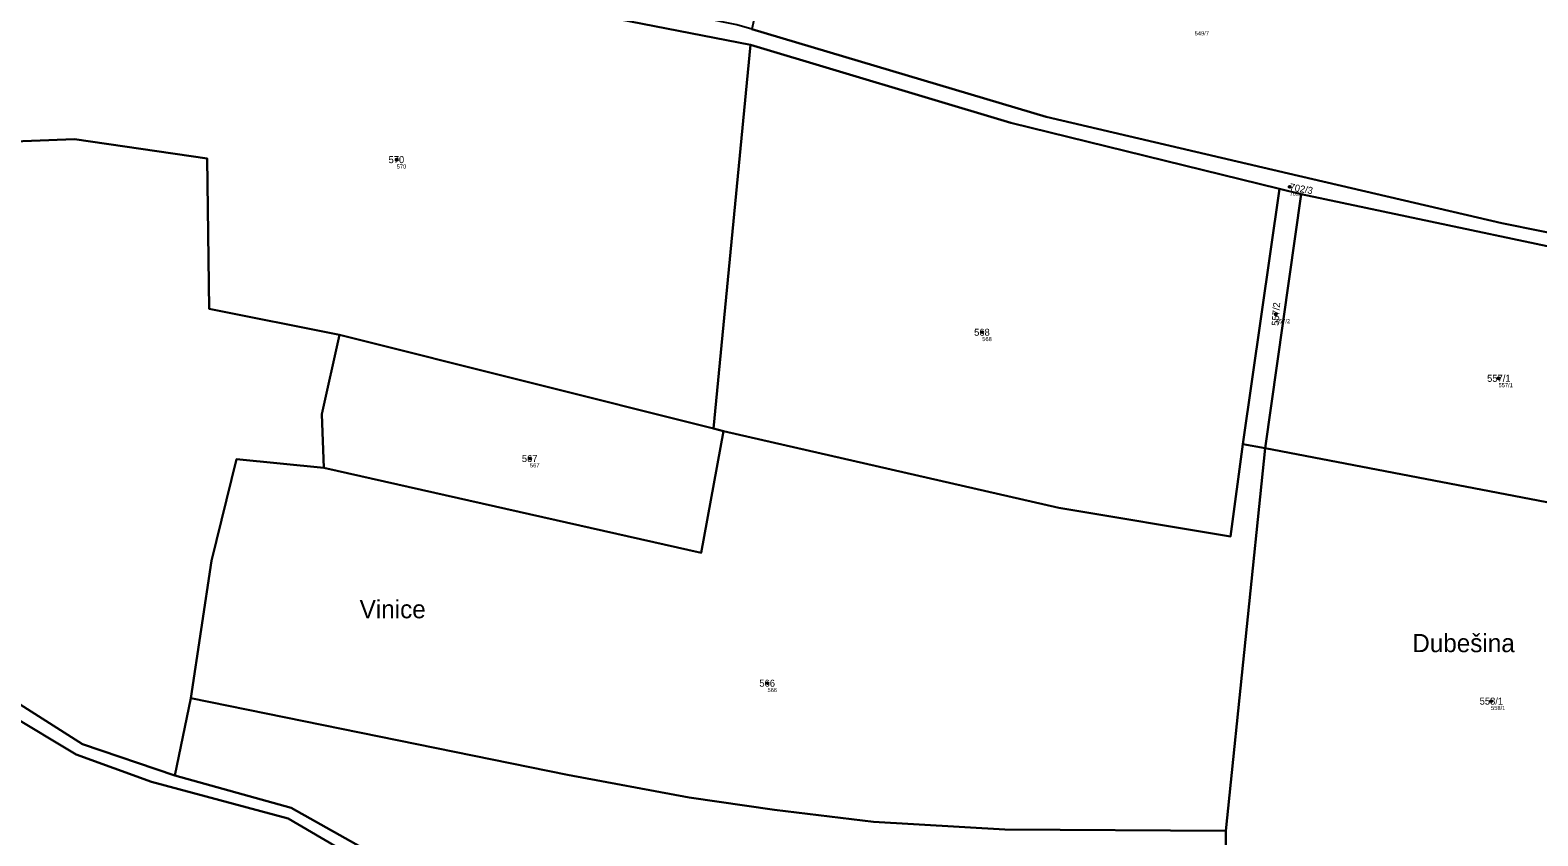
# Model space of a CAD drawing. Extents: x -767985 to -763816, y -1059600 to -1057360.
# Drawn here: x -764545.8 to -764180.2, y -1058967.5 to -1058772.1 of the extents above; entities that cross this region are included whole.
import ezdxf

# ---------------------------------------------------------------- set-up
doc = ezdxf.new("R2010")
doc.units = 0
for name, color, linetype in [('Definiční body', 7, 'Continuous'), ('Hranice parcel', 7, 'Continuous'), ('Parcelní čísla', 7, 'Continuous'), ('Polygon parcely', 7, 'Continuous'), ('Pop  PČ popisy', 7, 'Continuous')]:
    doc.layers.add(name, color=color, linetype=linetype)

msp = doc.modelspace()

# ---------------------------------------------------------------- linework, layer by layer
at = {"layer": 'Definiční body'}
for centre in [(-764456.89, -1058803.50994), (-764240.38, -1058810.07994), (-764243.73, -1058841.01994), (-764314.92, -1058845.35994), (-764189.75, -1058856.52994), (-764424.57, -1058875.97994), (-764366.99, -1058930.44994), (-764191.56, -1058934.78994)]:
    msp.add_circle(centre, 0.25, dxfattribs=at)
at = {"layer": 'Hranice parcel'}
for p, q in [((-764371.09, -1058775.68), (-764380.09, -1058868.72)), ((-764242.88, -1058810.57), (-764251.71, -1058872.53)), ((-764237.59, -1058811.87), (-764246.31, -1058873.43)), ((-764242.88, -1058810.57), (-764237.59, -1058811.87)), ((-764380.09, -1058868.72), (-764470.72, -1058846.01)), ((-764377.65, -1058869.33), (-764380.09, -1058868.72)), ((-764246.31, -1058873.43), (-764255.86, -1058966.23)), ((-764251.71, -1058872.53), (-764246.31, -1058873.43)), ((-764246.31, -1058873.43), (-764129.55, -1058895.82)), ((-764506.78, -1058934.04), (-764510.68, -1058952.79)), ((-764255.86, -1058966.23), (-764255.54, -1058994.61))]:
    msp.add_line(p, q, dxfattribs=at)
for points in [[(-764504.93, -1058762.17), (-764465.63, -1058763.92), (-764435.08, -1058763.17), (-764371.09, -1058775.68)], [(-764117.67, -1058835.76), (-764150.51, -1058826.7), (-764188.92, -1058818.94), (-764240.71, -1058806.89), (-764299.39, -1058793.13), (-764370.8, -1058771.89)], [(-764371.09, -1058775.68), (-764307.98, -1058794.62), (-764242.88, -1058810.57)], [(-764639.47, -1058805.04), (-764597.53, -1058801), (-764535.04, -1058798.52), (-764502.82, -1058803.24), (-764502.32, -1058839.71), (-764470.72, -1058846.01)], [(-764237.59, -1058811.87), (-764145.03, -1058831.46), (-764115.57, -1058839.6)], [(-764470.72, -1058846.01), (-764475.06, -1058865.2), (-764474.53, -1058878.21)], [(-764377.65, -1058869.33), (-764383.09, -1058898.84), (-764474.53, -1058878.21)], [(-764251.71, -1058872.53), (-764254.71, -1058894.86), (-764296.36, -1058887.95), (-764377.65, -1058869.33)], [(-764474.53, -1058878.21), (-764495.74, -1058876.16), (-764501.82, -1058900.74), (-764506.78, -1058934.04)], [(-764647.54, -1058894.05), (-764602.1, -1058910.08), (-764554.5, -1058931.66), (-764533.08, -1058945.22), (-764510.68, -1058952.79)], [(-764255.86, -1058966.23), (-764309.43, -1058965.95), (-764341.31, -1058964.1), (-764365.33, -1058961.14), (-764385.95, -1058958.19), (-764415.5, -1058952.65), (-764506.78, -1058934.04)], [(-764422.1, -1059006.07), (-764428.85, -1058998.23), (-764454.9, -1058979.8), (-764483.17, -1058963.28), (-764516.36, -1058954.39), (-764534.62, -1058947.71), (-764550.97, -1058937.86)], [(-764510.68, -1058952.79), (-764482.48, -1058960.66), (-764454.96, -1058976.1), (-764426.01, -1058996.65)]]:
    msp.add_lwpolyline(points, dxfattribs=at)
at = {"layer": 'Polygon parcely'}
for points in [[(-764117.67, -1058835.76), (-764103.91, -1058762.69), (-764129.87, -1058759.06), (-764182.87, -1058751.21), (-764258.28, -1058733.41), (-764257.68, -1058705.09), (-764257.42, -1058693.02), (-764257.49, -1058680.02), (-764315.15, -1058690.29), (-764317.45, -1058720.72), (-764358.5, -1058715.78), (-764370.8, -1058771.89), (-764299.39, -1058793.13), (-764240.71, -1058806.89), (-764188.92, -1058818.94), (-764150.51, -1058826.7)], [(-764565.32, -1058769.17), (-764617.02, -1058785.39), (-764638.77, -1058784.8), (-764639.47, -1058805.04), (-764597.53, -1058801), (-764535.04, -1058798.52), (-764502.82, -1058803.24), (-764502.32, -1058839.71), (-764470.72, -1058846.01), (-764380.09, -1058868.72), (-764371.09, -1058775.68), (-764435.08, -1058763.17), (-764465.63, -1058763.92), (-764504.93, -1058762.17), (-764531.81, -1058764.14), (-764546.46, -1058766.71)], [(-764371.09, -1058775.68), (-764380.09, -1058868.72), (-764377.65, -1058869.33), (-764296.36, -1058887.95), (-764254.71, -1058894.86), (-764251.71, -1058872.53), (-764242.88, -1058810.57), (-764307.98, -1058794.62)], [(-764554.5, -1058931.66), (-764533.08, -1058945.22), (-764510.68, -1058952.79), (-764506.78, -1058934.04), (-764501.82, -1058900.74), (-764495.74, -1058876.16), (-764474.53, -1058878.21), (-764475.06, -1058865.2), (-764470.72, -1058846.01), (-764502.32, -1058839.71), (-764502.82, -1058803.24), (-764535.04, -1058798.52), (-764597.53, -1058801), (-764639.47, -1058805.04), (-764643.69, -1058840.03), (-764644.74, -1058862.37), (-764647.54, -1058894.05), (-764602.1, -1058910.08)], [(-764251.71, -1058872.53), (-764246.31, -1058873.43), (-764237.59, -1058811.87), (-764242.88, -1058810.57)], [(-764129.55, -1058895.82), (-764124.14, -1058870.68), (-764115.57, -1058839.6), (-764145.03, -1058831.46), (-764237.59, -1058811.87), (-764246.31, -1058873.43)], [(-764475.06, -1058865.2), (-764474.53, -1058878.21), (-764383.09, -1058898.84), (-764377.65, -1058869.33), (-764380.09, -1058868.72), (-764470.72, -1058846.01)], [(-764501.82, -1058900.74), (-764506.78, -1058934.04), (-764415.5, -1058952.65), (-764385.95, -1058958.19), (-764365.33, -1058961.14), (-764341.31, -1058964.1), (-764309.43, -1058965.95), (-764255.86, -1058966.23), (-764246.31, -1058873.43), (-764251.71, -1058872.53), (-764254.71, -1058894.86), (-764296.36, -1058887.95), (-764377.65, -1058869.33), (-764383.09, -1058898.84), (-764474.53, -1058878.21), (-764495.74, -1058876.16)], [(-764133.76, -1058962.77), (-764131.29, -1058923.53), (-764129.55, -1058895.82), (-764246.31, -1058873.43), (-764255.86, -1058966.23), (-764255.54, -1058994.61), (-764215.38, -1058993.24), (-764138.31, -1058991.9)], [(-764647.72, -1058896.12), (-764600.3, -1058914.3), (-764550.97, -1058937.86), (-764534.62, -1058947.71), (-764516.36, -1058954.39), (-764483.17, -1058963.28), (-764454.9, -1058979.8), (-764428.85, -1058998.23), (-764422.1, -1059006.07), (-764419.54, -1059005.59), (-764426.01, -1058996.65), (-764454.96, -1058976.1), (-764482.48, -1058960.66), (-764510.68, -1058952.79), (-764533.08, -1058945.22), (-764554.5, -1058931.66), (-764602.1, -1058910.08), (-764647.54, -1058894.05)], [(-764385.95, -1058958.19), (-764415.5, -1058952.65), (-764506.78, -1058934.04), (-764510.68, -1058952.79), (-764482.48, -1058960.66), (-764454.96, -1058976.1), (-764426.01, -1058996.65), (-764363.85, -1058997.35), (-764307.58, -1058996.13), (-764255.54, -1058994.61), (-764255.86, -1058966.23), (-764309.43, -1058965.95), (-764341.31, -1058964.1), (-764365.33, -1058961.14)], [(-764573.5, -1059077.29), (-764572, -1059077.35), (-764574.27, -1059110.44), (-764575.79, -1059132.56), (-764553.86, -1059135.67), (-764528.62, -1059138.32), (-764507.61, -1059139.04), (-764504.32, -1059119.13), (-764500.98, -1059107.77), (-764498.75, -1059094.63), (-764496.53, -1059064.78), (-764497.42, -1059020.24), (-764422.1, -1059006.07), (-764428.85, -1058998.23), (-764454.9, -1058979.8), (-764483.17, -1058963.28), (-764516.36, -1058954.39), (-764534.62, -1058947.71), (-764550.97, -1058937.86), (-764553.99, -1058960.4), (-764565.74, -1058995.14), (-764571.94, -1059044.52)]]:
    msp.add_lwpolyline(points, close=True, dxfattribs=at)
msp.add_lwpolyline([(-764150.51, -1058826.7), (-764188.92, -1058818.94), (-764240.71, -1058806.89), (-764299.39, -1058793.13), (-764370.8, -1058771.89), (-764374.44, -1058770.8), (-764424.43, -1058760.67), (-764439.19, -1058755.57), (-764504.93, -1058762.17), (-764465.63, -1058763.92), (-764435.08, -1058763.17), (-764371.09, -1058775.68), (-764307.98, -1058794.62), (-764242.88, -1058810.57), (-764237.59, -1058811.87), (-764145.03, -1058831.46)], dxfattribs=at)

# ---------------------------------------------------------------- texts
at = {"layer": 'Definiční body'}
for s, p in [('549/7', (-764263.42, -1058773.396)), ('570', (-764456.89, -1058805.666)), ('702/3', (-764240.38, -1058812.236)), ('557/2', (-764243.73, -1058843.176)), ('568', (-764314.92, -1058847.516)), ('557/1', (-764189.75, -1058858.686)), ('567', (-764424.57, -1058878.136)), ('566', (-764366.99, -1058932.606)), ('558/1', (-764191.56, -1058936.946))]:
    msp.add_text(s, height=0.999996, dxfattribs=at).set_placement(p)
at = {"layer": 'Parcelní čísla'}
for s, p in [('570', (-764458.864, -1058804.36)), ('568', (-764316.894, -1058846.21)), ('557/1', (-764192.523, -1058857.38)), ('567', (-764426.544, -1058876.83)), ('566', (-764368.964, -1058931.3)), ('558/1', (-764194.333, -1058935.64))]:
    msp.add_text(s, height=1.699998, dxfattribs=at).set_placement(p)
for s, rotation, p in [('702/3', 349.9999972, (-764240.527, -1058810.917)), ('557/2', 86, (-764243.075, -1058843.845))]:
    msp.add_text(s, height=1.699998, rotation=rotation, dxfattribs=at).set_placement(p)
at = {"layer": 'Pop  PČ popisy'}
for s, p in [('Vinice', (-764465.87, -1058914.71)), ('Dubešina', (-764210.67, -1058922.919))]:
    msp.add_text(s, height=4.399998, dxfattribs=at).set_placement(p)

doc.saveas('drawing.dxf')
